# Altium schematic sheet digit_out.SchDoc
size A2
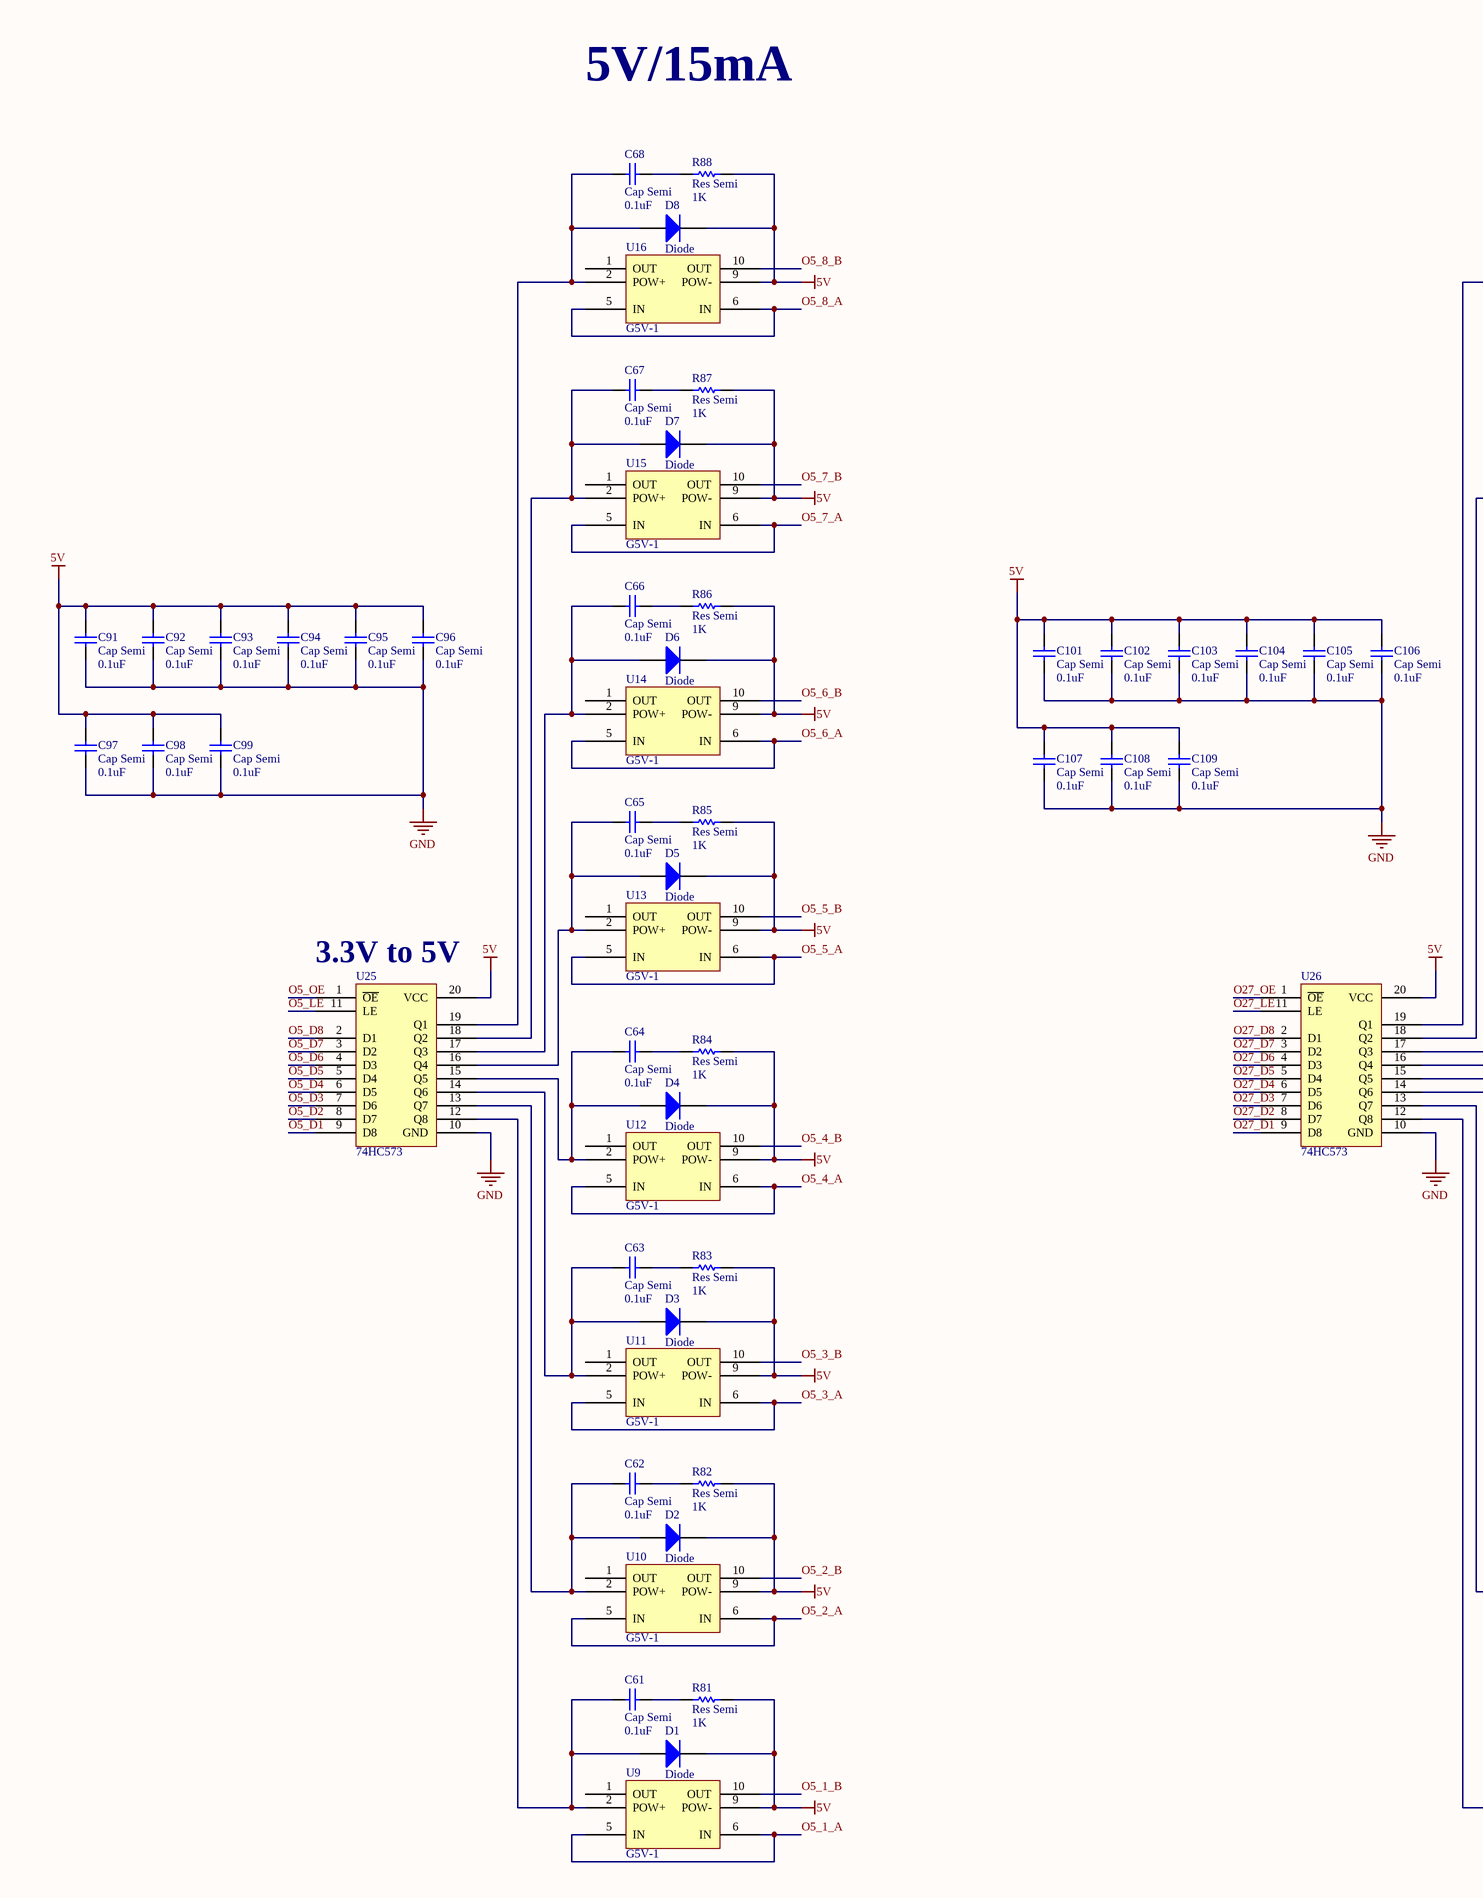
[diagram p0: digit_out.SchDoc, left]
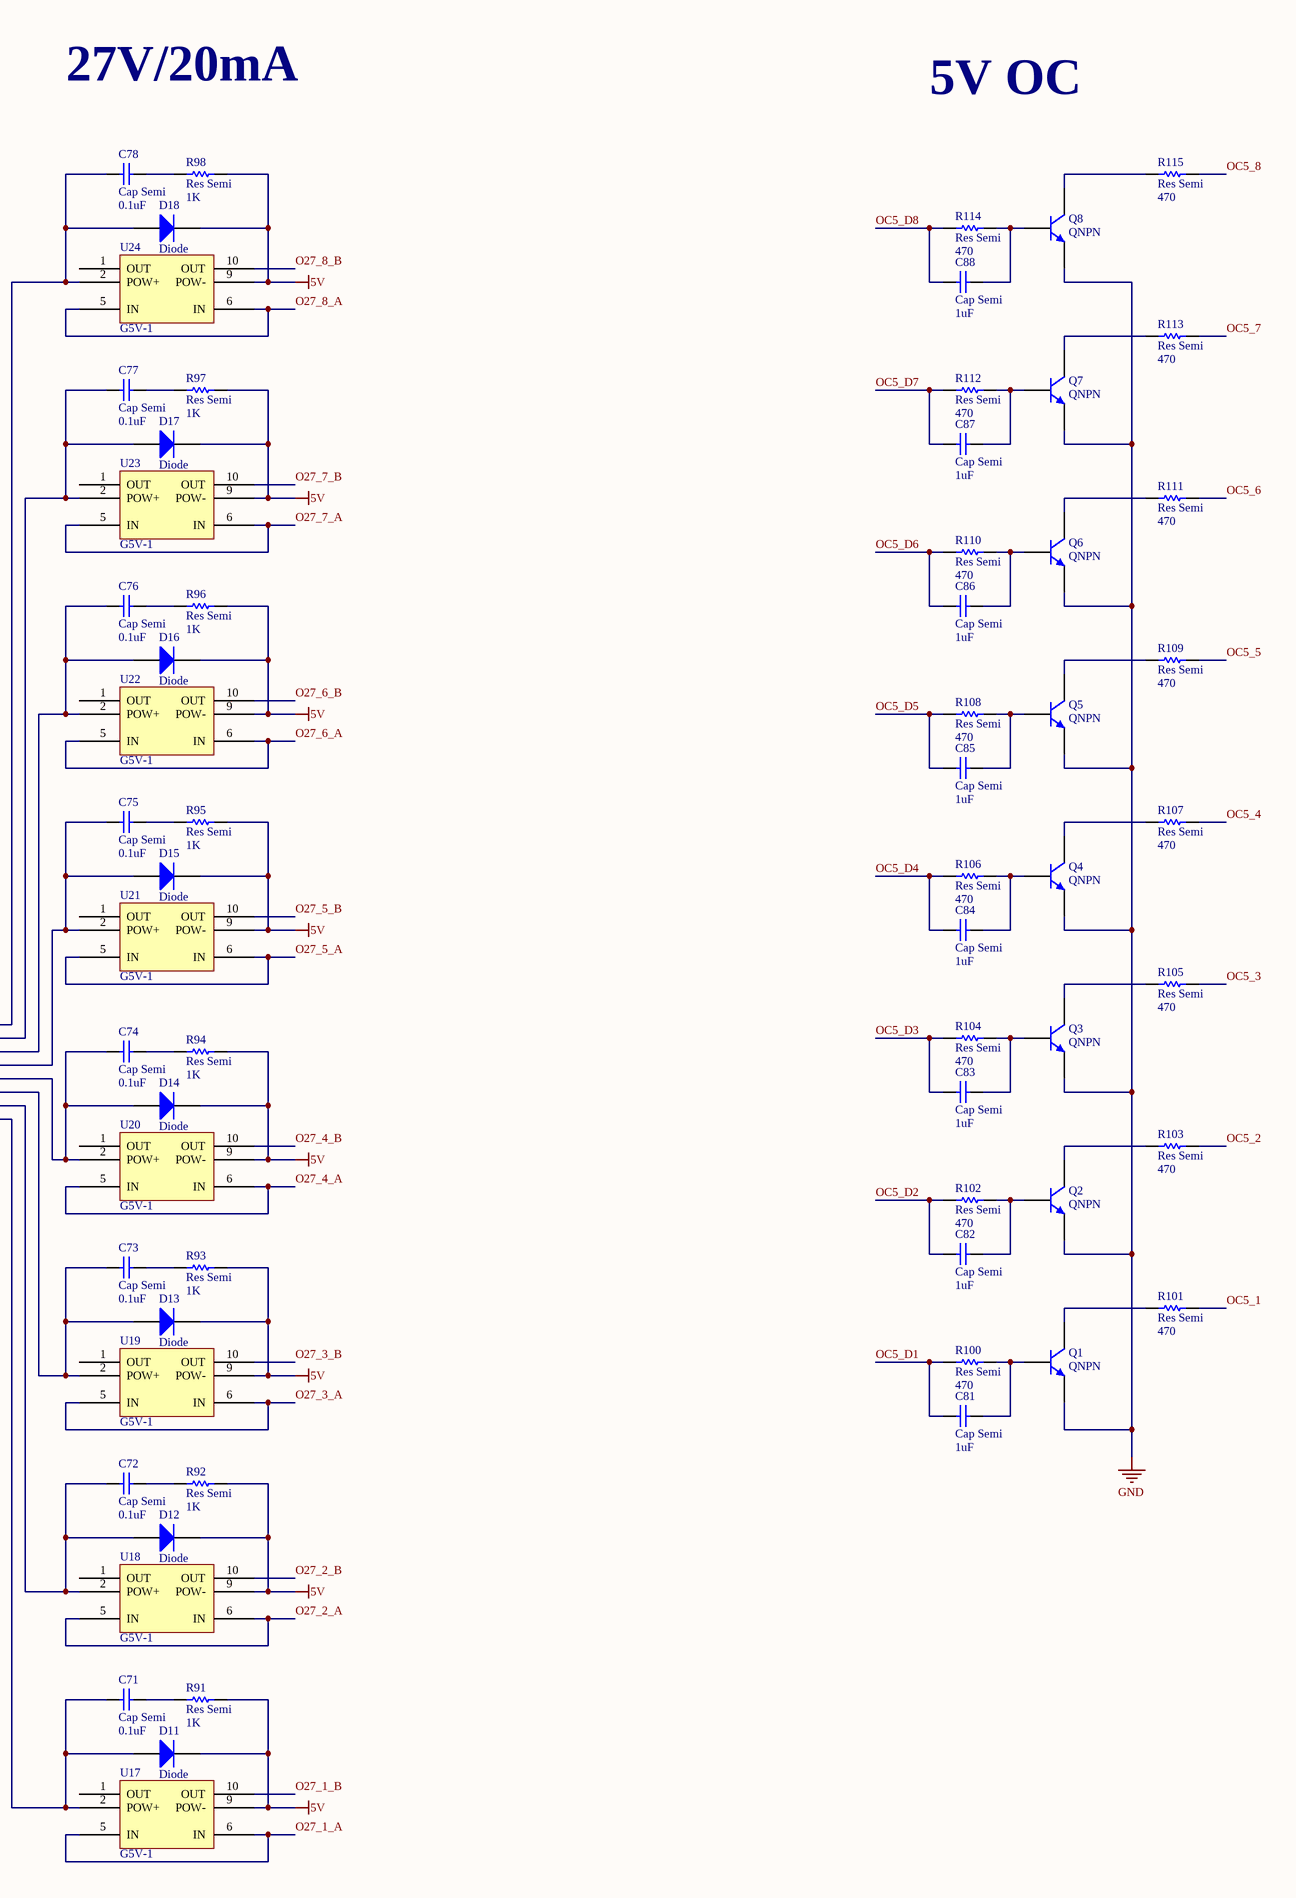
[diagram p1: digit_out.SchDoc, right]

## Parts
C61  Cap Semi  value 0.1uF  [1608[0603]]
C62  Cap Semi  value 0.1uF  [1608[0603]]
C63  Cap Semi  value 0.1uF  [1608[0603]]
C64  Cap Semi  value 0.1uF  [1608[0603]]
C65  Cap Semi  value 0.1uF  [1608[0603]]
C66  Cap Semi  value 0.1uF  [1608[0603]]
C67  Cap Semi  value 0.1uF  [1608[0603]]
C68  Cap Semi  value 0.1uF  [1608[0603]]
C71  Cap Semi  value 0.1uF  [1608[0603]]
C72  Cap Semi  value 0.1uF  [1608[0603]]
C73  Cap Semi  value 0.1uF  [1608[0603]]
C74  Cap Semi  value 0.1uF  [1608[0603]]
C75  Cap Semi  value 0.1uF  [1608[0603]]
C76  Cap Semi  value 0.1uF  [1608[0603]]
C77  Cap Semi  value 0.1uF  [1608[0603]]
C78  Cap Semi  value 0.1uF  [1608[0603]]
C81  Cap Semi  value 1uF  [1608[0603]]
C82  Cap Semi  value 1uF  [1608[0603]]
C83  Cap Semi  value 1uF  [1608[0603]]
C84  Cap Semi  value 1uF  [1608[0603]]
C85  Cap Semi  value 1uF  [1608[0603]]
C86  Cap Semi  value 1uF  [1608[0603]]
C87  Cap Semi  value 1uF  [1608[0603]]
C88  Cap Semi  value 1uF  [1608[0603]]
C91  Cap Semi  value 0.1uF  [1608[0603]]
C92  Cap Semi  value 0.1uF  [1608[0603]]
C93  Cap Semi  value 0.1uF  [1608[0603]]
C94  Cap Semi  value 0.1uF  [1608[0603]]
C95  Cap Semi  value 0.1uF  [1608[0603]]
C96  Cap Semi  value 0.1uF  [1608[0603]]
C97  Cap Semi  value 0.1uF  [1608[0603]]
C98  Cap Semi  value 0.1uF  [1608[0603]]
C99  Cap Semi  value 0.1uF  [1608[0603]]
C101  Cap Semi  value 0.1uF  [1608[0603]]
C102  Cap Semi  value 0.1uF  [1608[0603]]
C103  Cap Semi  value 0.1uF  [1608[0603]]
C104  Cap Semi  value 0.1uF  [1608[0603]]
C105  Cap Semi  value 0.1uF  [1608[0603]]
C106  Cap Semi  value 0.1uF  [1608[0603]]
C107  Cap Semi  value 0.1uF  [1608[0603]]
C108  Cap Semi  value 0.1uF  [1608[0603]]
C109  Cap Semi  value 0.1uF  [1608[0603]]
D1  Diode  [IN5817]
D2  Diode  [IN5817]
D3  Diode  [IN5817]
D4  Diode  [IN5817]
D5  Diode  [IN5817]
D6  Diode  [IN5817]
D7  Diode  [IN5817]
D8  Diode  [IN5817]
D11  Diode  [IN5817]
D12  Diode  [IN5817]
D13  Diode  [IN5817]
D14  Diode  [IN5817]
D15  Diode  [IN5817]
D16  Diode  [IN5817]
D17  Diode  [IN5817]
D18  Diode  [IN5817]
Q1  QNPN  [SO3]
Q2  QNPN  [SO3]
Q3  QNPN  [SO3]
Q4  QNPN  [SO3]
Q5  QNPN  [SO3]
Q6  QNPN  [SO3]
Q7  QNPN  [SO3]
Q8  QNPN  [SO3]
R81  Res Semi  value 1K  [1608[0603]]
R82  Res Semi  value 1K  [1608[0603]]
R83  Res Semi  value 1K  [1608[0603]]
R84  Res Semi  value 1K  [1608[0603]]
R85  Res Semi  value 1K  [1608[0603]]
R86  Res Semi  value 1K  [1608[0603]]
R87  Res Semi  value 1K  [1608[0603]]
R88  Res Semi  value 1K  [1608[0603]]
R91  Res Semi  value 1K  [1608[0603]]
R92  Res Semi  value 1K  [1608[0603]]
R93  Res Semi  value 1K  [1608[0603]]
R94  Res Semi  value 1K  [1608[0603]]
R95  Res Semi  value 1K  [1608[0603]]
R96  Res Semi  value 1K  [1608[0603]]
R97  Res Semi  value 1K  [1608[0603]]
R98  Res Semi  value 1K  [1608[0603]]
R100  Res Semi  value 470  [1608[0603]]
R101  Res Semi  value 470  [1608[0603]]
R102  Res Semi  value 470  [1608[0603]]
R103  Res Semi  value 470  [1608[0603]]
R104  Res Semi  value 470  [1608[0603]]
R105  Res Semi  value 470  [1608[0603]]
R106  Res Semi  value 470  [1608[0603]]
R107  Res Semi  value 470  [1608[0603]]
R108  Res Semi  value 470  [1608[0603]]
R109  Res Semi  value 470  [1608[0603]]
R110  Res Semi  value 470  [1608[0603]]
R111  Res Semi  value 470  [1608[0603]]
R112  Res Semi  value 470  [1608[0603]]
R113  Res Semi  value 470  [1608[0603]]
R114  Res Semi  value 470  [1608[0603]]
R115  Res Semi  value 470  [1608[0603]]
U9  G5V-1  [G5V-1-DIP]
U10  G5V-1  [G5V-1-DIP]
U11  G5V-1  [G5V-1-DIP]
U12  G5V-1  [G5V-1-DIP]
U13  G5V-1  [G5V-1-DIP]
U14  G5V-1  [G5V-1-DIP]
U15  G5V-1  [G5V-1-DIP]
U16  G5V-1  [G5V-1-DIP]
U17  G5V-1  [G5V-1-DIP]
U18  G5V-1  [G5V-1-DIP]
U19  G5V-1  [G5V-1-DIP]
U20  G5V-1  [G5V-1-DIP]
U21  G5V-1  [G5V-1-DIP]
U22  G5V-1  [G5V-1-DIP]
U23  G5V-1  [G5V-1-DIP]
U24  G5V-1  [G5V-1-DIP]
U25  74HC573  [SOP20]
U26  74HC573  [SOP20]

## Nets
5V: C91.2 C92.2 C93.2 C94.2 C95.2 C96.2 C97.2 C98.2 C99.2 C101.2 C102.2 C103.2 C104.2 C105.2 C106.2 C107.2 C108.2 C109.2 D1.2(K) D2.2(K) D3.2(K) D4.2(K) D5.2(K) D6.2(K) D7.2(K) D8.2(K) D11.2(K) D12.2(K) D13.2(K) D14.2(K) D15.2(K) D16.2(K) D17.2(K) D18.2(K) R81.2 R82.2 R83.2 R84.2 R85.2 R86.2 R87.2 R88.2 R91.2 R92.2 R93.2 R94.2 R95.2 R96.2 R97.2 R98.2 U9.9(POW-) U10.9(POW-) U11.9(POW-) U12.9(POW-) U13.9(POW-) U14.9(POW-) U15.9(POW-) U16.9(POW-) U17.9(POW-) U18.9(POW-) U19.9(POW-) U20.9(POW-) U21.9(POW-) U22.9(POW-) U23.9(POW-) U24.9(POW-) U25.20(VCC) U26.20(VCC)
GND: C91.1 C92.1 C93.1 C94.1 C95.1 C96.1 C97.1 C98.1 C99.1 C101.1 C102.1 C103.1 C104.1 C105.1 C106.1 C107.1 C108.1 C109.1 Q1.3(E) Q2.3(E) Q3.3(E) Q4.3(E) Q5.3(E) Q6.3(E) Q7.3(E) Q8.3(E) U25.10(GND) U26.10(GND)
O5_1_A: U9.5(IN) U9.6(IN)
O5_1_B: U9.10(OUT)
O5_2_A: U10.5(IN) U10.6(IN)
O5_2_B: U10.10(OUT)
O5_3_A: U11.5(IN) U11.6(IN)
O5_3_B: U11.10(OUT)
O5_4_A: U12.5(IN) U12.6(IN)
O5_4_B: U12.10(OUT)
O5_5_A: U13.5(IN) U13.6(IN)
O5_5_B: U13.10(OUT)
O5_6_A: U14.5(IN) U14.6(IN)
O5_6_B: U14.10(OUT)
O5_7_A: U15.5(IN) U15.6(IN)
O5_7_B: U15.10(OUT)
O5_8_A: U16.5(IN) U16.6(IN)
O5_8_B: U16.10(OUT)
O5_D1: U25.9(D8)
O5_D2: U25.8(D7)
O5_D3: U25.7(D6)
O5_D4: U25.6(D5)
O5_D5: U25.5(D4)
O5_D6: U25.4(D3)
O5_D7: U25.3(D2)
O5_D8: U25.2(D1)
O5_LE: U25.11(LE)
O5_OE: U25.1(~{OE})
O27_1_A: U17.5(IN) U17.6(IN)
O27_1_B: U17.10(OUT)
O27_2_A: U18.5(IN) U18.6(IN)
O27_2_B: U18.10(OUT)
O27_3_A: U19.5(IN) U19.6(IN)
O27_3_B: U19.10(OUT)
O27_4_A: U20.5(IN) U20.6(IN)
O27_4_B: U20.10(OUT)
O27_5_A: U21.5(IN) U21.6(IN)
O27_5_B: U21.10(OUT)
O27_6_A: U22.5(IN) U22.6(IN)
O27_6_B: U22.10(OUT)
O27_7_A: U23.5(IN) U23.6(IN)
O27_7_B: U23.10(OUT)
O27_8_A: U24.5(IN) U24.6(IN)
O27_8_B: U24.10(OUT)
O27_D1: U26.9(D8)
O27_D2: U26.8(D7)
O27_D3: U26.7(D6)
O27_D4: U26.6(D5)
O27_D5: U26.5(D4)
O27_D6: U26.4(D3)
O27_D7: U26.3(D2)
O27_D8: U26.2(D1)
O27_LE: U26.11(LE)
O27_OE: U26.1(~{OE})
OC5_1: R101.2
OC5_2: R103.2
OC5_3: R105.2
OC5_4: R107.2
OC5_5: R109.2
OC5_6: R111.2
OC5_7: R113.2
OC5_8: R115.2
OC5_D1: C81.2 R100.1
OC5_D2: C82.2 R102.1
OC5_D3: C83.2 R104.1
OC5_D4: C84.2 R106.1
OC5_D5: C85.2 R108.1
OC5_D6: C86.2 R110.1
OC5_D7: C87.2 R112.1
OC5_D8: C88.2 R114.1
NetC61_1: C61.1 R81.1
NetC61_2: C61.2 D1.1(A) U9.2(POW+) U25.12(Q8)
NetC62_1: C62.1 R82.1
NetC62_2: C62.2 D2.1(A) U10.2(POW+) U25.13(Q7)
NetC63_1: C63.1 R83.1
NetC63_2: C63.2 D3.1(A) U11.2(POW+) U25.14(Q6)
NetC64_1: C64.1 R84.1
NetC64_2: C64.2 D4.1(A) U12.2(POW+) U25.15(Q5)
NetC65_1: C65.1 R85.1
NetC65_2: C65.2 D5.1(A) U13.2(POW+) U25.16(Q4)
NetC66_1: C66.1 R86.1
NetC66_2: C66.2 D6.1(A) U14.2(POW+) U25.17(Q3)
NetC67_1: C67.1 R87.1
NetC67_2: C67.2 D7.1(A) U15.2(POW+) U25.18(Q2)
NetC68_1: C68.1 R88.1
NetC68_2: C68.2 D8.1(A) U16.2(POW+) U25.19(Q1)
NetC71_1: C71.1 R91.1
NetC71_2: C71.2 D11.1(A) U17.2(POW+) U26.12(Q8)
NetC72_1: C72.1 R92.1
NetC72_2: C72.2 D12.1(A) U18.2(POW+) U26.13(Q7)
NetC73_1: C73.1 R93.1
NetC73_2: C73.2 D13.1(A) U19.2(POW+) U26.14(Q6)
NetC74_1: C74.1 R94.1
NetC74_2: C74.2 D14.1(A) U20.2(POW+) U26.15(Q5)
NetC75_1: C75.1 R95.1
NetC75_2: C75.2 D15.1(A) U21.2(POW+) U26.16(Q4)
NetC76_1: C76.1 R96.1
NetC76_2: C76.2 D16.1(A) U22.2(POW+) U26.17(Q3)
NetC77_1: C77.1 R97.1
NetC77_2: C77.2 D17.1(A) U23.2(POW+) U26.18(Q2)
NetC78_1: C78.1 R98.1
NetC78_2: C78.2 D18.1(A) U24.2(POW+) U26.19(Q1)
NetC81_1: C81.1 Q1.2(B) R100.2
NetC82_1: C82.1 Q2.2(B) R102.2
NetC83_1: C83.1 Q3.2(B) R104.2
NetC84_1: C84.1 Q4.2(B) R106.2
NetC85_1: C85.1 Q5.2(B) R108.2
NetC86_1: C86.1 Q6.2(B) R110.2
NetC87_1: C87.1 Q7.2(B) R112.2
NetC88_1: C88.1 Q8.2(B) R114.2
NetQ1_1: Q1.1(C) R101.1
NetQ2_1: Q2.1(C) R103.1
NetQ3_1: Q3.1(C) R105.1
NetQ4_1: Q4.1(C) R107.1
NetQ5_1: Q5.1(C) R109.1
NetQ6_1: Q6.1(C) R111.1
NetQ7_1: Q7.1(C) R113.1
NetQ8_1: Q8.1(C) R115.1

Not connected (* = marked no-connect by the designer): U9 1(OUT); U10 1(OUT); U11 1(OUT); U12 1(OUT); U13 1(OUT); U14 1(OUT); U15 1(OUT); U16 1(OUT); U17 1(OUT); U18 1(OUT); U19 1(OUT); U20 1(OUT); U21 1(OUT); U22 1(OUT); U23 1(OUT); U24 1(OUT)

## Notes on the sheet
- 5V/15mA
- 27V/20mA
- 5V OC
- (near U25) 3.3V to 5V

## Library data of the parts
C61-C68 C71-C78 C81-C88 C91-C99 C101-C109 = Cap Semi: Capacitor (Semiconductor SIM Model)
D1-D8 D11-D18 = Diode: Default Diode
Q1-Q8 = QNPN: NPN Bipolar Transistor
R81-R88 R91-R98 R100-R115 = Res Semi: Semiconductor Resistor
